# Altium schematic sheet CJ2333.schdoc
size 127 x 101 mm
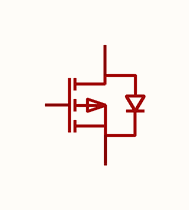
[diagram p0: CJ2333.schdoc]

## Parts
Q?  cj2333  [SOT-23-3_L3.0-W1.7-P0.95-LS2.9-BR]  (value not drawn)

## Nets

Not connected (* = marked no-connect by the designer): Q? 1(G) 2(S) 3(D)

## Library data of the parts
Q? = cj2333: 数量:1个P沟道;漏源电压(Vdss):12V;连续漏极电流(Id):6A;导通电阻(RDS(on)):28mΩ@4.5V;耗散功率(Pd):1.1W;阈值电压(Vgs(th)):400mV;; Manufacturer: CJ(江苏长电/长晶); AddInBom: yes; ModelId: 89cb27a44ab2466697082bb9fd73a7d0; ModelName: SOT-23-3L_L2.9-W1.6-H1.1-LS2.8-P0.95; ModelTransform: 114.173,110.236,0,90,0,0,0,0,0; Number: 1个P沟道; Drain to Source Voltage: 12V; Current - Continuous Drain(Id): 6A; Pd - Power Dissipation: 1.1W; Gate Threshold Voltage (Vgs(th)): 400mV; Gate Charge(Qg): 21nC@4.5V; Input Capacitance(Ciss): 1.275nF; Reverse Transfer Capacitance (Crss@Vds): 236pF; Type: P沟道; Output Capacitance(Coss): 255pF; Vgs: ±8V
